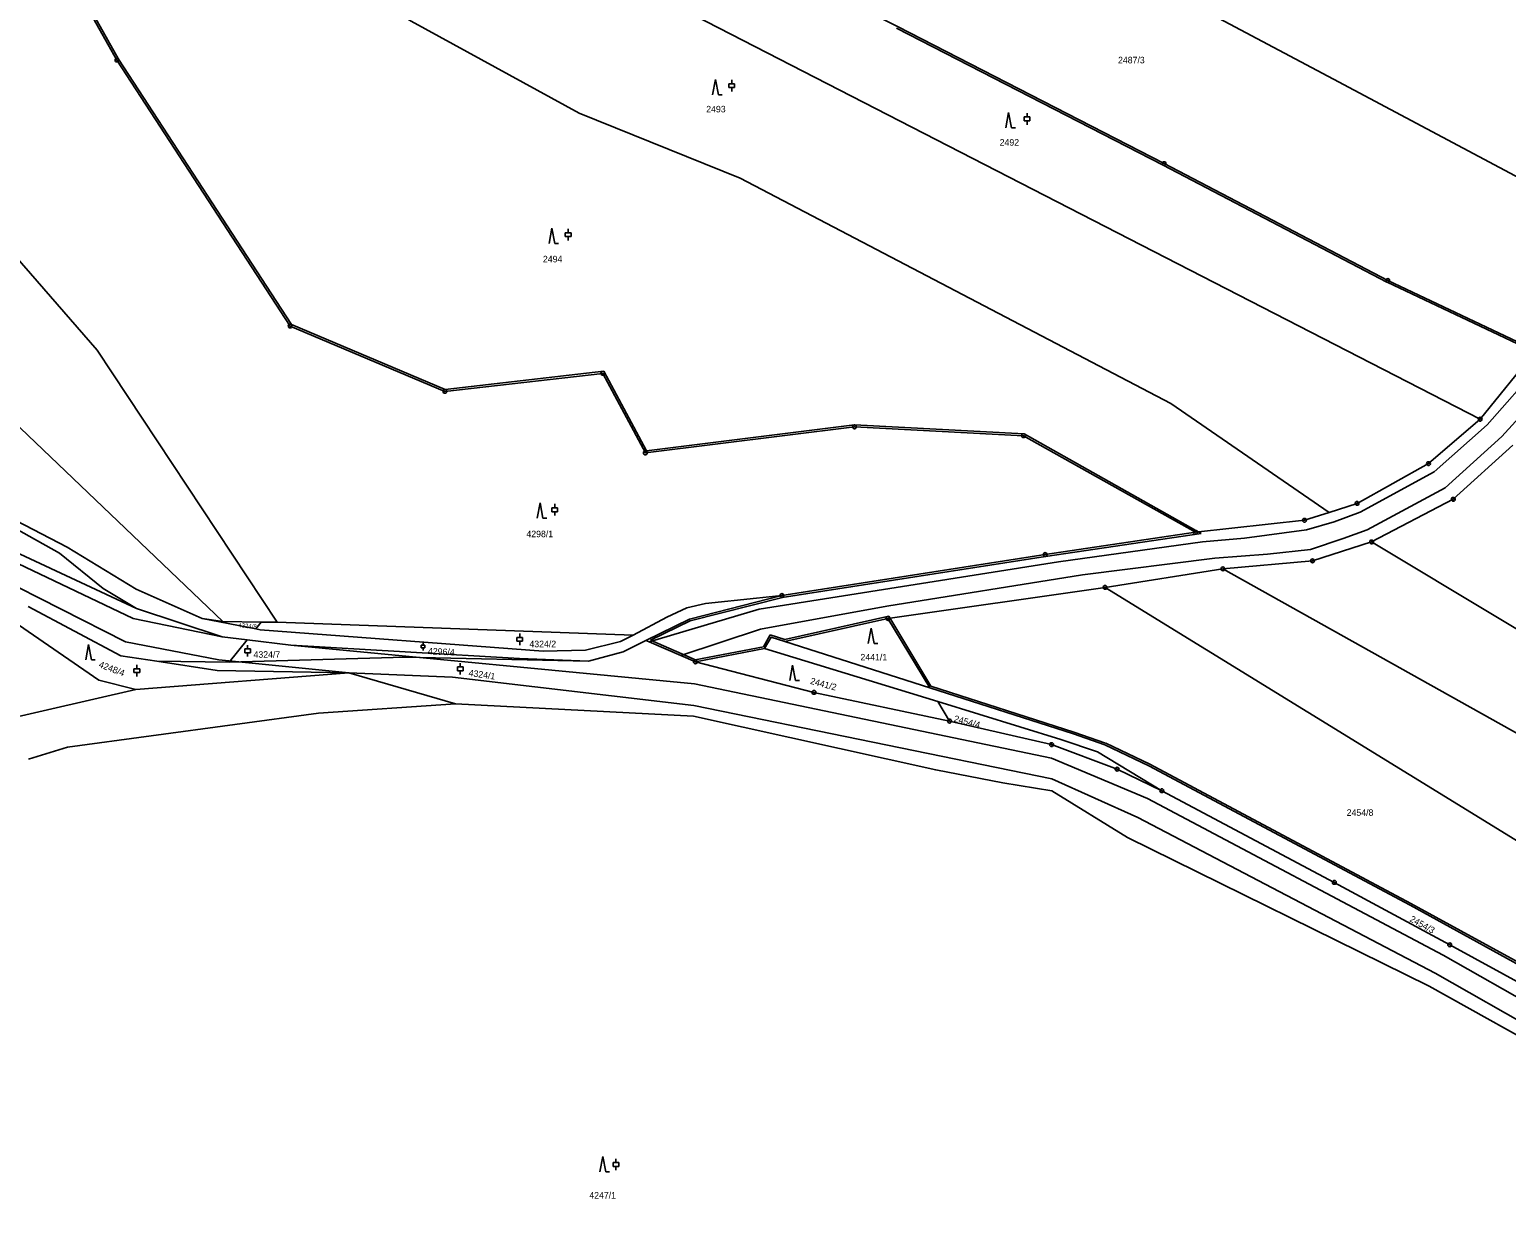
# Model space of a CAD drawing. Extents: x -733394 to -722299, y -1082822 to -1075049.
# Drawn here: x -730270.6 to -729886.1, y -1079209.2 to -1078897.3 of the extents above; entities that cross this region are included whole.
import ezdxf

# ---------------------------------------------------------------- set-up
doc = ezdxf.new("R2010")
doc.units = 0
for name, color, linetype in [('Hranice parcel', 7, 'Continuous'), ('Parcelní čísla', 7, 'Continuous'), ('Vnitřní kresba', 7, 'Continuous'), ('Značky bodu BP', 7, 'Continuous'), ('Značky kultur', 7, 'Continuous')]:
    doc.layers.add(name, color=color, linetype=linetype)

msp = doc.modelspace()

# ---------------------------------------------------------------- linework, layer by layer
at = {"layer": 'Hranice parcel'}
for p, q in [((-730143.12, -1078870.09), (-729892.92, -1078998.75)), ((-729878.45, -1078980.81), (-729892.92, -1078998.75)), ((-729959.89, -1079037.72), (-729990.58, -1079042.53)), ((-729990.58, -1079042.53), (-730047.13, -1079050.62)), ((-730225.67, -1079050.63), (-730220.3, -1079051.38)), ((-730211.71, -1079053.37), (-730225.67, -1079050.63)), ((-730220.3, -1079051.38), (-730210.25, -1079051.55)), ((-730047.13, -1079050.62), (-730073.97, -1079056.67)), ((-730036.24, -1079068.72), (-730047.13, -1079050.62)), ((-730210.25, -1079051.55), (-730211.71, -1079053.37)), ((-730210.25, -1079051.55), (-730206.09, -1079051.62)), ((-730206.09, -1079051.62), (-730113.4, -1079054.94)), ((-730218.64, -1079062.03), (-730213.95, -1079056.17)), ((-730079.21, -1079058.44), (-730097.24, -1079061.91)), ((-730034.09, -1079072.29), (-730079.21, -1079058.44)), ((-730073.97, -1079056.67), (-730036.24, -1079068.72)), ((-730218.64, -1079062.03), (-730237.49, -1079061.77)), ((-730187.44, -1079064.82), (-730242.93, -1079069.1)), ((-730187.44, -1079064.82), (-730159.67, -1079072.84)), ((-730031.05, -1079077.35), (-730034.09, -1079072.29))]:
    msp.add_line(p, q, dxfattribs=at)
for points in [[(-729844.69, -1078956.24), (-729931.07, -1078910.16), (-730006.5, -1078870.08), (-730064.77, -1078842.54), (-730108.94, -1078820.75)], [(-730265.83, -1078838.22), (-730171.26, -1078895.08), (-730127.47, -1078919.01), (-730085.54, -1078935.96), (-729973.44, -1078994.66), (-729932.21, -1079023)], [(-730127.73, -1078855.32), (-730085.5, -1078876.02), (-730044.65, -1078896.51), (-729975.19, -1078932.19), (-729916.95, -1078962.64), (-729878.45, -1078980.81)], [(-730258.02, -1078887.15), (-730247.84, -1078905.22), (-730202.74, -1078974.49), (-730162.48, -1078991.5), (-730121.34, -1078986.81), (-730110.27, -1079007.52), (-730055.8, -1079000.75), (-730011.81, -1079003.05), (-729967.07, -1079028.2)], [(-730325.47, -1078897.54), (-730252.97, -1078980.77), (-730206.09, -1079051.62)], [(-730220.3, -1079051.38), (-730276.87, -1078997.34), (-730319.12, -1078950.28), (-730353.32, -1078913.76)], [(-730468.18, -1078920.03), (-730465.75, -1078928.55), (-730464.38, -1078931.01), (-730459.9, -1078933.77), (-730442.68, -1078938.26), (-730414.37, -1078950.81), (-730399.31, -1078960.22), (-730383.18, -1078971.41), (-730352.3, -1078990.18), (-730310.2, -1079009.22), (-730285.28, -1079019.38), (-730260.82, -1079032.1), (-730242.86, -1079042.97), (-730225.67, -1079050.63)], [(-730470.48, -1078922.89), (-730468.42, -1078930.03), (-730466.24, -1078932.71), (-730461.12, -1078935.86), (-730443.4, -1078940.73), (-730415.74, -1078952.84), (-730400.84, -1078962.18), (-730384.48, -1078973.37), (-730353.53, -1078992.02), (-730311.15, -1079011.26), (-730300.32, -1079015.83), (-730278.7, -1079024.76), (-730262.77, -1079033.64), (-730251.39, -1079042.83), (-730242.75, -1079048.07)], [(-730437.32, -1078965.7), (-730427.85, -1078969.29), (-730369.28, -1078991.3), (-730346.93, -1078999.67), (-730313.54, -1079014.58), (-730287.59, -1079027.14), (-730242.75, -1079048.07)], [(-729892.92, -1078998.75), (-729906.38, -1079010.31), (-729924.97, -1079020.67), (-729932.21, -1079023)], [(-729884.41, -1079005.5), (-729899.92, -1079019.6), (-729921.18, -1079030.71)], [(-729932.21, -1079023), (-729938.67, -1079025.07), (-729967.07, -1079028.2)], [(-729967.07, -1079028.2), (-730006.18, -1079033.99), (-730074.72, -1079044.65)], [(-730242.93, -1079069.1), (-730252.57, -1079066.71), (-730303.65, -1079031.5)], [(-729921.18, -1079030.71), (-729936.59, -1079035.61), (-729959.89, -1079037.72)], [(-729357.49, -1079261.51), (-729437.08, -1079255), (-729495.32, -1079243.6), (-729524.89, -1079235.04), (-729628.01, -1079188.26), (-729704.88, -1079148.47), (-729722.87, -1079142.97), (-729771.48, -1079119.13), (-729853.9, -1079071.16), (-729921.18, -1079030.71)], [(-729605.38, -1079228.29), (-729624.73, -1079215.71), (-729662.57, -1079195.52), (-729715.69, -1079169.63), (-729799.8, -1079128.73), (-729872.12, -1079086.79), (-729959.89, -1079037.72)], [(-729812.96, -1079152.16), (-729885.02, -1079107.49), (-729990.58, -1079042.53)], [(-730237.49, -1079061.77), (-730246.85, -1079060.34), (-730270.92, -1079047.54)], [(-730074.72, -1079044.65), (-730081.37, -1079045.36), (-730094.57, -1079046.69), (-730099.47, -1079047.84), (-730104.67, -1079050.29), (-730113.4, -1079054.94)], [(-730110.12, -1079056.36), (-730098.78, -1079050.77), (-730074.72, -1079044.65)], [(-730242.75, -1079048.07), (-730220.41, -1079055.39), (-730213.95, -1079056.17)], [(-730113.4, -1079054.94), (-730116.74, -1079056.59), (-730125.81, -1079058.85), (-730136.88, -1079059.14), (-730210.52, -1079053.6), (-730211.71, -1079053.37)], [(-730213.95, -1079056.17), (-730202.61, -1079057.54), (-730143.01, -1079061.07), (-730125.09, -1079061.74)], [(-730125.09, -1079061.74), (-730116.07, -1079059.29), (-730110.12, -1079056.36)], [(-730110.12, -1079056.36), (-730109.29, -1079056.7), (-730101.01, -1079060.27), (-730097.24, -1079061.91)], [(-730073.97, -1079056.67), (-730077.52, -1079055.53), (-730079.21, -1079058.44)], [(-730237.49, -1079061.77), (-730221.75, -1079064.18), (-730187.44, -1079064.82)], [(-730125.09, -1079061.74), (-730172.86, -1079060.74), (-730218.64, -1079062.03)], [(-730097.24, -1079061.91), (-730066.36, -1079069.88), (-730031.05, -1079077.35)], [(-730242.93, -1079069.1), (-730277.96, -1079077.24), (-730291.2, -1079084.32)], [(-729822.58, -1079173.44), (-729836.7, -1079166.23), (-729911.18, -1079125.25), (-729979.16, -1079089), (-729990.6, -1079083.54), (-729998.83, -1079080.68), (-730036.24, -1079068.72)], [(-730270.87, -1079087.31), (-730260.7, -1079084.1), (-730195.36, -1079075.26), (-730159.67, -1079072.84)], [(-730159.67, -1079072.84), (-730097.73, -1079076.08), (-730034.68, -1079090.05), (-730017.22, -1079093.41), (-730004.46, -1079095.48), (-729984.77, -1079107.69), (-729906.16, -1079146.4), (-729835.21, -1079185.94), (-729815.2, -1079195.27), (-729777.18, -1079211.74), (-729735.96, -1079223.43)], [(-730034.09, -1079072.29), (-730002.07, -1079082.12), (-729992.53, -1079085.4), (-729975.81, -1079095.48)], [(-730031.05, -1079077.35), (-730004.5, -1079083.48), (-729987.45, -1079089.87), (-729975.81, -1079095.48)], [(-729975.81, -1079095.48), (-729930.89, -1079119.35), (-729900.85, -1079135.6), (-729824.48, -1079177.4), (-729772.8, -1079199.43), (-729751.64, -1079206.12), (-729732.54, -1079210.19)]]:
    msp.add_lwpolyline(points, dxfattribs=at)
at = {"layer": 'Vnitřní kresba'}
for p, q in [((-730257.58, -1078886.9), (-730247.4, -1078904.97)), ((-730044.88, -1078896.95), (-729975.42, -1078932.63)), ((-730247.42, -1078904.95), (-730202.4, -1078974.09)), ((-729975.42, -1078932.63), (-729917.18, -1078963.08)), ((-729917.16, -1078963.09), (-729878.4, -1078981.39)), ((-730202.4, -1078974.09), (-730162.41, -1078990.99)), ((-729891.09, -1079000.2), (-729876.45, -1078983.57)), ((-730121.06, -1078986.27), (-730162.41, -1078990.99)), ((-730121.06, -1078986.27), (-730109.99, -1079006.98)), ((-729873.28, -1078987.82), (-729887.24, -1079003.26)), ((-730109.99, -1079006.98), (-730055.82, -1079000.25)), ((-730055.82, -1079000.25), (-730011.67, -1079002.56)), ((-729904.86, -1079012.49), (-729891.09, -1079000.2)), ((-730011.67, -1079002.56), (-729965.55, -1079028.48)), ((-729887.24, -1079003.26), (-729902.02, -1079016.58)), ((-729924.12, -1079022.92), (-729904.86, -1079012.49)), ((-729902.02, -1079016.58), (-729922.38, -1079027.52)), ((-729930.95, -1079025.46), (-729924.12, -1079022.92)), ((-729954.24, -1079029.72), (-729938.17, -1079027.57)), ((-729938.17, -1079027.57), (-729930.95, -1079025.46)), ((-729922.38, -1079027.52), (-729928.56, -1079029.84)), ((-730288.64, -1079029.18), (-730243.59, -1079050.6)), ((-730006.11, -1079034.48), (-729965.55, -1079028.48)), ((-730002.68, -1079035.9), (-729965.2, -1079030.7)), ((-729965.2, -1079030.7), (-729954.24, -1079029.72)), ((-729928.56, -1079029.84), (-729937.13, -1079032.67)), ((-730290.98, -1079033.71), (-730245.65, -1079056.75)), ((-730080.64, -1079048.17), (-730002.68, -1079035.9)), ((-730006.1, -1079034.48), (-730074.64, -1079045.14)), ((-729996.48, -1079039.3), (-729962.01, -1079034.95)), ((-729948.31, -1079033.89), (-729962.01, -1079034.95)), ((-729937.13, -1079032.67), (-729948.31, -1079033.89)), ((-729996.48, -1079039.3), (-730047.4, -1079047.4)), ((-730098.6, -1079051.24), (-730074.6, -1079045.13)), ((-730047.4, -1079047.4), (-730080.27, -1079053.39)), ((-730243.59, -1079050.6), (-730220.41, -1079055.39)), ((-730109.29, -1079056.7), (-730080.64, -1079048.17)), ((-730098.6, -1079051.24), (-730108.91, -1079056.32)), ((-730073.95, -1079056.15), (-730046.89, -1079050.05)), ((-730046.89, -1079050.05), (-730035.91, -1079068.3)), ((-730080.27, -1079053.39), (-730101.01, -1079060.27)), ((-730077.75, -1079054.93), (-730079.53, -1079057.99)), ((-730073.95, -1079056.15), (-730077.75, -1079054.93)), ((-730245.65, -1079056.75), (-730221.33, -1079061.41)), ((-730202.61, -1079057.54), (-730097.44, -1079067.61)), ((-730108.91, -1079056.32), (-730100.81, -1079059.81)), ((-730097.33, -1079061.42), (-730079.53, -1079057.99)), ((-730221.33, -1079061.41), (-730187.44, -1079064.82)), ((-730100.81, -1079059.81), (-730097.04, -1079061.45)), ((-730187.44, -1079064.82), (-730160.46, -1079065.91)), ((-730160.46, -1079065.91), (-730097.63, -1079073.29)), ((-730097.44, -1079067.61), (-730004.49, -1079087)), ((-729998.68, -1079080.2), (-730035.91, -1079068.3)), ((-730097.63, -1079073.29), (-730004.47, -1079092.4)), ((-729998.67, -1079080.21), (-729990.44, -1079083.07)), ((-729990.38, -1079083.09), (-729978.94, -1079088.55)), ((-730004.49, -1079087), (-729979.51, -1079097.5)), ((-729978.92, -1079088.56), (-729910.94, -1079124.81)), ((-729982.05, -1079102.42), (-730004.47, -1079092.4)), ((-729979.51, -1079097.5), (-729902.53, -1079138.29)), ((-729904.64, -1079143), (-729982.05, -1079102.42)), ((-729910.94, -1079124.81), (-729836.46, -1079165.79)), ((-729902.53, -1079138.29), (-729831.83, -1079178.48)), ((-729834.02, -1079183.31), (-729904.64, -1079143))]:
    msp.add_line(p, q, dxfattribs=at)
at = {"layer": 'Značky bodu BP'}
for centre, radius in [((-730247.84, -1078905.22), 0.5), ((-730247.84, -1078905.22), 0.0303), ((-729975.19, -1078932.19), 0.5), ((-729975.19, -1078932.19), 0.0303), ((-729916.95, -1078962.64), 0.5), ((-729916.95, -1078962.64), 0.0303), ((-730202.74, -1078974.49), 0.5), ((-730202.74, -1078974.49), 0.0303), ((-730121.34, -1078986.81), 0.5), ((-730121.34, -1078986.81), 0.0303), ((-730162.48, -1078991.5), 0.5), ((-730162.48, -1078991.5), 0.0303), ((-730055.8, -1079000.75), 0.5), ((-730055.8, -1079000.75), 0.0303), ((-729892.92, -1078998.75), 0.5), ((-729892.92, -1078998.75), 0.0303), ((-730011.81, -1079003.05), 0.5), ((-730011.81, -1079003.05), 0.0303), ((-730110.27, -1079007.52), 0.5), ((-730110.27, -1079007.52), 0.0303), ((-729906.38, -1079010.31), 0.5), ((-729906.38, -1079010.31), 0.0303), ((-729924.97, -1079020.67), 0.5), ((-729924.97, -1079020.67), 0.0303), ((-729899.92, -1079019.6), 0.5), ((-729899.92, -1079019.6), 0.0303), ((-729967.07, -1079028.2), 0.5), ((-729967.07, -1079028.2), 0.0303), ((-729938.67, -1079025.07), 0.5), ((-729938.67, -1079025.07), 0.0303), ((-729921.18, -1079030.71), 0.5), ((-729921.18, -1079030.71), 0.0303), ((-730006.18, -1079033.99), 0.5), ((-730006.18, -1079033.99), 0.0303), ((-729936.59, -1079035.61), 0.5), ((-729936.59, -1079035.61), 0.0303), ((-729959.89, -1079037.72), 0.5), ((-729959.89, -1079037.72), 0.0303), ((-729990.58, -1079042.53), 0.5), ((-729990.58, -1079042.53), 0.0303), ((-730074.72, -1079044.65), 0.5), ((-730074.72, -1079044.65), 0.0303), ((-730047.13, -1079050.62), 0.5), ((-730047.13, -1079050.62), 0.0303), ((-730097.24, -1079061.91), 0.5), ((-730097.24, -1079061.91), 0.0303), ((-730066.36, -1079069.88), 0.5), ((-730066.36, -1079069.88), 0.0303), ((-730031.05, -1079077.35), 0.5), ((-730031.05, -1079077.35), 0.0303), ((-730004.5, -1079083.48), 0.5), ((-730004.5, -1079083.48), 0.0303), ((-729987.45, -1079089.87), 0.5), ((-729987.45, -1079089.87), 0.0303), ((-729975.81, -1079095.48), 0.5), ((-729975.81, -1079095.48), 0.0303), ((-729930.89, -1079119.35), 0.5), ((-729930.89, -1079119.35), 0.5), ((-729930.89, -1079119.35), 0.0303), ((-729930.89, -1079119.35), 0.0303), ((-729900.85, -1079135.6), 0.5), ((-729900.85, -1079135.6), 0.5), ((-729900.85, -1079135.6), 0.5), ((-729900.85, -1079135.6), 0.5), ((-729900.85, -1079135.6), 0.0303), ((-729900.85, -1079135.6), 0.0303), ((-729900.85, -1079135.6), 0.0303), ((-729900.85, -1079135.6), 0.0303)]:
    msp.add_circle(centre, radius, dxfattribs=at)
at = {"layer": 'Značky kultur'}
for p, q in [((-730092.01, -1078910.29), (-730092.76, -1078914.29)), ((-730091.26, -1078914.29), (-730092.01, -1078910.29)), ((-730088.53, -1078911.39), (-730087.03, -1078911.39)), ((-730088.53, -1078912.39), (-730088.53, -1078911.39)), ((-730088.53, -1078912.39), (-730087.03, -1078912.39)), ((-730087.78, -1078911.39), (-730087.78, -1078910.39)), ((-730087.78, -1078913.39), (-730087.78, -1078912.39)), ((-730087.03, -1078912.39), (-730087.03, -1078911.39)), ((-730091.26, -1078914.29), (-730090.26, -1078914.29)), ((-730015.68, -1078918.88), (-730016.43, -1078922.88)), ((-730014.93, -1078922.88), (-730015.68, -1078918.88)), ((-730011.64, -1078920.05), (-730010.14, -1078920.05)), ((-730011.64, -1078921.05), (-730011.64, -1078920.05)), ((-730010.89, -1078920.05), (-730010.89, -1078919.05)), ((-730010.14, -1078921.05), (-730010.14, -1078920.05)), ((-730014.93, -1078922.88), (-730013.93, -1078922.88)), ((-730011.64, -1078921.05), (-730010.14, -1078921.05)), ((-730010.89, -1078922.05), (-730010.89, -1078921.05)), ((-730134.6, -1078949.03), (-730135.35, -1078953.03)), ((-730133.85, -1078953.03), (-730134.6, -1078949.03)), ((-730131.12, -1078950.19), (-730129.62, -1078950.19)), ((-730131.12, -1078951.19), (-730131.12, -1078950.19)), ((-730131.12, -1078951.19), (-730129.62, -1078951.19)), ((-730130.37, -1078950.19), (-730130.37, -1078949.19)), ((-730130.37, -1078952.19), (-730130.37, -1078951.19)), ((-730129.62, -1078951.19), (-730129.62, -1078950.19)), ((-730133.85, -1078953.03), (-730132.85, -1078953.03)), ((-730137.67, -1079020.55), (-730138.42, -1079024.55)), ((-730136.92, -1079024.55), (-730137.67, -1079020.55)), ((-730136.92, -1079024.55), (-730135.92, -1079024.55)), ((-730134.61, -1079021.82), (-730133.11, -1079021.82)), ((-730134.61, -1079022.82), (-730134.61, -1079021.82)), ((-730134.61, -1079022.82), (-730133.11, -1079022.82)), ((-730133.86, -1079021.82), (-730133.86, -1079020.82)), ((-730133.86, -1079023.82), (-730133.86, -1079022.82)), ((-730133.11, -1079022.82), (-730133.11, -1079021.82)), ((-730142.96, -1079055.57), (-730142.96, -1079054.57)), ((-730051.47, -1079053.12), (-730052.22, -1079057.12)), ((-730050.72, -1079057.12), (-730051.47, -1079053.12)), ((-730255.23, -1079057.42), (-730255.98, -1079061.42)), ((-730254.48, -1079061.42), (-730255.23, -1079057.42)), ((-730214.56, -1079058.56), (-730213.06, -1079058.56)), ((-730214.56, -1079059.56), (-730214.56, -1079058.56)), ((-730213.81, -1079058.56), (-730213.81, -1079057.56)), ((-730213.06, -1079059.56), (-730213.06, -1079058.56)), ((-730168.65, -1079057.62), (-730167.65, -1079057.62)), ((-730168.65, -1079058.29), (-730168.65, -1079057.62)), ((-730168.65, -1079058.29), (-730167.65, -1079058.29)), ((-730168.15, -1079057.62), (-730168.15, -1079056.95)), ((-730168.15, -1079058.96), (-730168.15, -1079058.29)), ((-730167.65, -1079058.29), (-730167.65, -1079057.62)), ((-730143.71, -1079055.57), (-730142.21, -1079055.57)), ((-730143.71, -1079056.57), (-730143.71, -1079055.57)), ((-730143.71, -1079056.57), (-730142.21, -1079056.57)), ((-730142.96, -1079057.57), (-730142.96, -1079056.57)), ((-730142.21, -1079056.57), (-730142.21, -1079055.57)), ((-730050.72, -1079057.12), (-730049.72, -1079057.12)), ((-730254.48, -1079061.42), (-730253.48, -1079061.42)), ((-730242.65, -1079063.72), (-730242.65, -1079062.72)), ((-730214.56, -1079059.56), (-730213.06, -1079059.56)), ((-730213.81, -1079060.56), (-730213.81, -1079059.56)), ((-730158.44, -1079063.25), (-730158.44, -1079062.25)), ((-730071.92, -1079062.75), (-730072.67, -1079066.75)), ((-730071.17, -1079066.75), (-730071.92, -1079062.75)), ((-730243.4, -1079063.72), (-730241.9, -1079063.72)), ((-730243.4, -1079064.72), (-730243.4, -1079063.72)), ((-730243.4, -1079064.72), (-730241.9, -1079064.72)), ((-730242.65, -1079065.72), (-730242.65, -1079064.72)), ((-730241.9, -1079064.72), (-730241.9, -1079063.72)), ((-730159.19, -1079063.25), (-730157.69, -1079063.25)), ((-730159.19, -1079064.25), (-730159.19, -1079063.25)), ((-730159.19, -1079064.25), (-730157.69, -1079064.25)), ((-730158.44, -1079065.25), (-730158.44, -1079064.25)), ((-730157.69, -1079064.25), (-730157.69, -1079063.25)), ((-730071.17, -1079066.75), (-730070.17, -1079066.75)), ((-730121.34, -1079190.71), (-730122.09, -1079194.71)), ((-730120.59, -1079194.71), (-730121.34, -1079190.71)), ((-730118.67, -1079192.32), (-730117.17, -1079192.32)), ((-730118.67, -1079193.32), (-730118.67, -1079192.32)), ((-730118.67, -1079193.32), (-730117.17, -1079193.32)), ((-730117.92, -1079192.32), (-730117.92, -1079191.32)), ((-730117.92, -1079194.32), (-730117.92, -1079193.32)), ((-730117.17, -1079193.32), (-730117.17, -1079192.32)), ((-730120.59, -1079194.71), (-730119.59, -1079194.71))]:
    msp.add_line(p, q, dxfattribs=at)

# ---------------------------------------------------------------- texts
at = {"layer": 'Parcelní čísla'}
for s, p in [('2487/3', (-729987.21, -1078906.08)), ('2493', (-730094.42, -1078918.85)), ('2492', (-730018.02, -1078927.51)), ('2494', (-730136.94, -1078957.9)), ('4298/1', (-730141.23, -1079029.47)), ('4324/7', (-730212.28, -1079060.86)), ('4324/2', (-730140.45, -1079058.12)), ('2441/1', (-730054.26, -1079061.56)), ('2454/8', (-729927.67, -1079102.03)), ('4247/1', (-730124.86, -1079201.69))]:
    msp.add_text(s, height=1.7, dxfattribs=at).set_placement(p)
for s, height, rotation, p in [('4324/8', 1.139, 355, (-730216.28, -1079052.95)), ('4296/4', 1.7, 357, (-730166.91, -1079059.94)), ('4248/4', 1.7, 339, (-730252.72, -1079063.26)), ('4324/1', 1.7, 352, (-730156.35, -1079065.6)), ('2441/2', 1.7, 345, (-730067.47, -1079067.63)), ('2454/4', 1.7, 345, (-730030.07, -1079077.46)), ('2454/3', 1.7, 331, (-729911.43, -1079129.4))]:
    msp.add_text(s, height=height, rotation=rotation, dxfattribs=at).set_placement(p)

doc.saveas('drawing.dxf')
